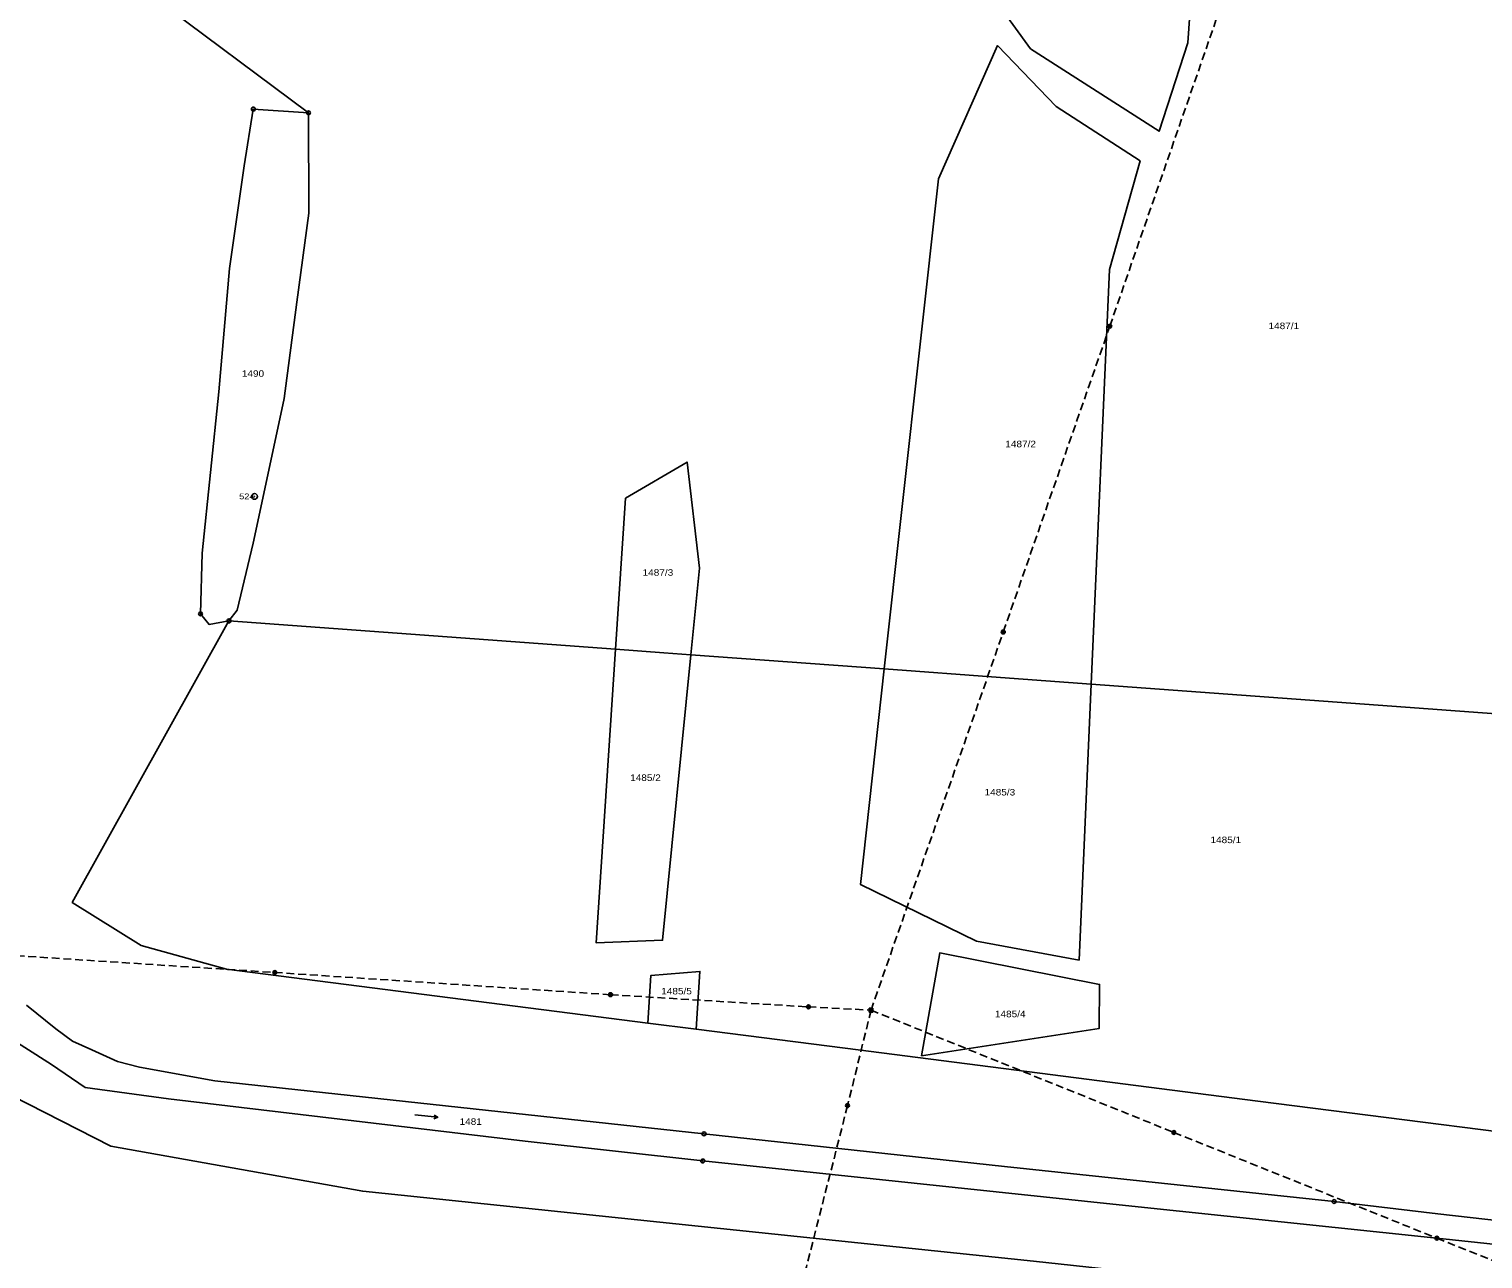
# Model space of a CAD drawing. Extents: x -872229 to -869198, y -1075981 to -1074329.
# Drawn here: x -871585.9 to -871207, y -1075209.5 to -1074889 of the extents above; entities that cross this region are included whole.
import ezdxf
from ezdxf.enums import TextEntityAlignment as Align

# ---------------------------------------------------------------- set-up
doc = ezdxf.new("R2010")
doc.units = 0
doc.header["$LTSCALE"] = 0.68
doc.linetypes.add('MEDIUM_DASHED', pattern=[4.5, 3, -1.5])
for name, color, linetype, lineweight in [('1', 7, 'Continuous', 25), ('3', 7, 'Continuous', 25), ('6', 7, 'Continuous', 25), ('8', 7, 'Continuous', 25)]:
    doc.layers.add(name, color=color, linetype=linetype, lineweight=lineweight)
doc.layers.add('2', color=7, linetype='Continuous')

msp = doc.modelspace()

# ---------------------------------------------------------------- linework, layer by layer
at = {"layer": '1'}
msp.add_line((-871513.08, -1074910.82), (-871584.85, -1074857.22), dxfattribs=at)
for points in [[(-871282.11, -1074866.22), (-871283.92, -1074892.6), (-871291.38, -1074915.63), (-871324.89, -1074894.16), (-871340.13, -1074873.1), (-871340.87, -1074864.14)], [(-871363.02, -1075055.76), (-871348.93, -1074928.05), (-871333.5, -1074893.3), (-871318.24, -1074909.17), (-871296.36, -1074923.36), (-871304.36, -1074951.64), (-871309.09, -1075059.71)], [(-871513.08, -1074910.82), (-871527.47, -1074909.84), (-871529.87, -1074924.66), (-871533.68, -1074951.43), (-871536.46, -1074983.57), (-871540.84, -1075025.59), (-871541.23, -1075041.38), (-871539.02, -1075044.15), (-871533.81, -1075043.24)], [(-871533.81, -1075043.24), (-871531.71, -1075040.41), (-871527.51, -1075022.97), (-871522.91, -1075001.53), (-871519.39, -1074985.24), (-871516.11, -1074960.17), (-871512.99, -1074936.96), (-871513.08, -1074910.82)], [(-871433.09, -1075050.62), (-871430.49, -1075011.26), (-871414.41, -1075001.84), (-871411.15, -1075029.47), (-871413.4, -1075052.07)], [(-871424.63, -1075148.05), (-871534.47, -1075134.02), (-871556.74, -1075127.83), (-871574.66, -1075116.59), (-871533.81, -1075043.24)], [(-871413.4, -1075052.07), (-871420.8, -1075126.47), (-871438.15, -1075127.13), (-871433.09, -1075050.62), (-871533.81, -1075043.24)], [(-871413.4, -1075052.07), (-871420.47, -1075051.55), (-871433.09, -1075050.62)], [(-871309.09, -1075059.71), (-871312.23, -1075131.62), (-871339.02, -1075126.74), (-871369.22, -1075111.94), (-871363.02, -1075055.76), (-871413.4, -1075052.07)], [(-871309.09, -1075059.71), (-871332.7, -1075057.98), (-871363.02, -1075055.76)], [(-871124.45, -1075073.24), (-871227.17, -1075065.71), (-871309.09, -1075059.71)], [(-871424.63, -1075148.05), (-871423.87, -1075135.7), (-871411.08, -1075134.58), (-871412.02, -1075149.67)], [(-871185.02, -1075201.57), (-871218.75, -1075197.81), (-871245.79, -1075194.55), (-871331.72, -1075185.46), (-871410.01, -1075176.94), (-871537.47, -1075163.08), (-871557.12, -1075159.53), (-871562.9, -1075158.08), (-871569.58, -1075155.03), (-871574.62, -1075152.74), (-871578.94, -1075149.53), (-871586.61, -1075143.41)], [(-871595.04, -1075149.42), (-871580.06, -1075158.85), (-871571.27, -1075164.84), (-871549.56, -1075167.77), (-871456.66, -1075178.8), (-871410.34, -1075183.99), (-871300.12, -1075195.6), (-871219.01, -1075204.11), (-871182.37, -1075208)], [(-871164.62, -1075181.27), (-871265.65, -1075168.37), (-871373.25, -1075154.62), (-871412.02, -1075149.67), (-871424.63, -1075148.05)], [(-871152.53, -1075228.75), (-871324.15, -1075210.15), (-871498.95, -1075191.88), (-871564.6, -1075180.17), (-871590.36, -1075167.06), (-871608.79, -1075266.42)]]:
    msp.add_lwpolyline(points, dxfattribs=at)
msp.add_lwpolyline([(-871353.31, -1075156.61), (-871348.55, -1075129.76), (-871306.92, -1075137.97), (-871307.02, -1075149.48)], close=True, dxfattribs=at)
at = {"layer": '3'}
msp.add_line((-871479.39, -1075172.624), (-871480.414, -1075173.02), dxfattribs=at)
msp.add_lwpolyline([(-871485.357, -1075171.997), (-871479.39, -1075172.624), (-871480.31, -1075172.023)], dxfattribs=at)
at = {"layer": '6', "linetype": 'MEDIUM_DASHED'}
for p, q in [((-871366.48, -1075144.68), (-871332.01, -1075046.13)), ((-871382.8, -1075143.84), (-871366.48, -1075144.68)), ((-871366.48, -1075144.68), (-871372.59, -1075169.57)), ((-871366.48, -1075144.68), (-871287.54, -1075176.57)), ((-871287.54, -1075176.57), (-871219.01, -1075204.11)), ((-871219.01, -1075204.11), (-871164.94, -1075225.78))]:
    msp.add_line(p, q, dxfattribs=at)
at = {"layer": '6'}
for p, q in [((-871366.982, -1075144.179), (-871365.981, -1075144.179)), ((-871366.982, -1075145.179), (-871366.982, -1075144.179)), ((-871366.982, -1075144.379), (-871365.981, -1075144.379)), ((-871366.982, -1075144.579), (-871365.981, -1075144.579)), ((-871366.982, -1075144.779), (-871365.981, -1075144.779)), ((-871366.982, -1075144.979), (-871365.981, -1075144.979)), ((-871366.982, -1075145.179), (-871365.981, -1075145.179)), ((-871366.781, -1075145.179), (-871366.781, -1075144.179)), ((-871366.582, -1075145.179), (-871366.582, -1075144.179)), ((-871366.381, -1075145.179), (-871366.381, -1075144.179)), ((-871366.182, -1075145.179), (-871366.182, -1075144.179)), ((-871365.981, -1075145.179), (-871365.981, -1075144.179))]:
    msp.add_line(p, q, dxfattribs=at)
at = {"layer": '6', "linetype": 'MEDIUM_DASHED'}
for points in [[(-871332.01, -1075046.13), (-871304.24, -1074966.42), (-871273.46, -1074877.72)], [(-871694.96, -1075123.52), (-871610.56, -1075129.11), (-871521.87, -1075134.87)], [(-871521.87, -1075134.87), (-871434.35, -1075140.66), (-871382.8, -1075143.84)], [(-871372.59, -1075169.57), (-871383.31, -1075211.56), (-871405.77, -1075298.4)]]:
    msp.add_lwpolyline(points, dxfattribs=at)
at = {"layer": '6'}
for centre, radius in [((-871304.2434, -1074966.4199), 0.5), ((-871304.2434, -1074966.4199), 0.4), ((-871304.2434, -1074966.4199), 0.3), ((-871304.2434, -1074966.4199), 0.2), ((-871304.2434, -1074966.4199), 0.1), ((-871332.0134, -1075046.1299), 0.5), ((-871332.0134, -1075046.1299), 0.4), ((-871332.0134, -1075046.1299), 0.3), ((-871332.0134, -1075046.1299), 0.2), ((-871332.0134, -1075046.1299), 0.1), ((-871521.8734, -1075134.8699), 0.5), ((-871521.8734, -1075134.8699), 0.4), ((-871521.8734, -1075134.8699), 0.3), ((-871521.8734, -1075134.8699), 0.2), ((-871521.8734, -1075134.8699), 0.1), ((-871434.3534, -1075140.6599), 0.5), ((-871434.3534, -1075140.6599), 0.4), ((-871434.3534, -1075140.6599), 0.3), ((-871434.3534, -1075140.6599), 0.2), ((-871434.3534, -1075140.6599), 0.1), ((-871382.8034, -1075143.8399), 0.5), ((-871382.8034, -1075143.8399), 0.4), ((-871382.8034, -1075143.8399), 0.3), ((-871382.8034, -1075143.8399), 0.2), ((-871382.8034, -1075143.8399), 0.1), ((-871372.5934, -1075169.5699), 0.5), ((-871372.5934, -1075169.5699), 0.4), ((-871372.5934, -1075169.5699), 0.3), ((-871372.5934, -1075169.5699), 0.2), ((-871372.5934, -1075169.5699), 0.1), ((-871287.5434, -1075176.5699), 0.5), ((-871287.5434, -1075176.5699), 0.4), ((-871287.5434, -1075176.5699), 0.3), ((-871287.5434, -1075176.5699), 0.2), ((-871287.5434, -1075176.5699), 0.1), ((-871219.0134, -1075204.1099), 0.5), ((-871219.0134, -1075204.1099), 0.4), ((-871219.0134, -1075204.1099), 0.3), ((-871219.0134, -1075204.1099), 0.2), ((-871219.0134, -1075204.1099), 0.1)]:
    msp.add_circle(centre, radius, dxfattribs=at)
at = {"layer": '8'}
for centre, radius in [((-871527.47, -1074909.8399), 0.5), ((-871527.47, -1074909.8399), 0.0303), ((-871513.08, -1074910.8199), 0.5), ((-871513.08, -1074910.8199), 0.0303), ((-871527.15, -1075010.7898), 0.75), ((-871527.15, -1075010.7898), 0.03), ((-871541.23, -1075041.3799), 0.5), ((-871541.23, -1075041.3799), 0.0303), ((-871533.81, -1075043.2399), 0.5), ((-871533.81, -1075043.2399), 0.0303), ((-871410.01, -1075176.9399), 0.5), ((-871410.01, -1075176.9399), 0.0303), ((-871410.34, -1075183.9899), 0.5), ((-871410.34, -1075183.9899), 0.0303), ((-871245.79, -1075194.5499), 0.5), ((-871245.79, -1075194.5499), 0.0303)]:
    msp.add_circle(centre, radius, dxfattribs=at)

# ---------------------------------------------------------------- texts
at = {"layer": '2', "width": 1.15}
for s, p in [('1487/1', (-871262.88, -1074967.19)), ('1490', (-871530.47, -1074979.62)), ('1487/2', (-871331.48, -1074997.98)), ('1487/3', (-871426.02, -1075031.47)), ('1485/2', (-871429.26, -1075084.95)), ('1485/3', (-871336.89, -1075088.74)), ('1485/1', (-871278.01, -1075101.16)), ('1485/5', (-871421.16, -1075140.59)), ('1485/4', (-871334.19, -1075146.54)), ('1481', (-871473.72, -1075174.59))]:
    msp.add_text(s, height=1.7, dxfattribs=at).set_placement(p)
at = {"layer": '8', "width": 1.2}
msp.add_text('524', height=1.5, dxfattribs=at).set_placement((-871527.15, -1075011.54), align=Align.RIGHT)

doc.saveas('drawing.dxf')
